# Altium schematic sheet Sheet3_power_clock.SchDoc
size A3
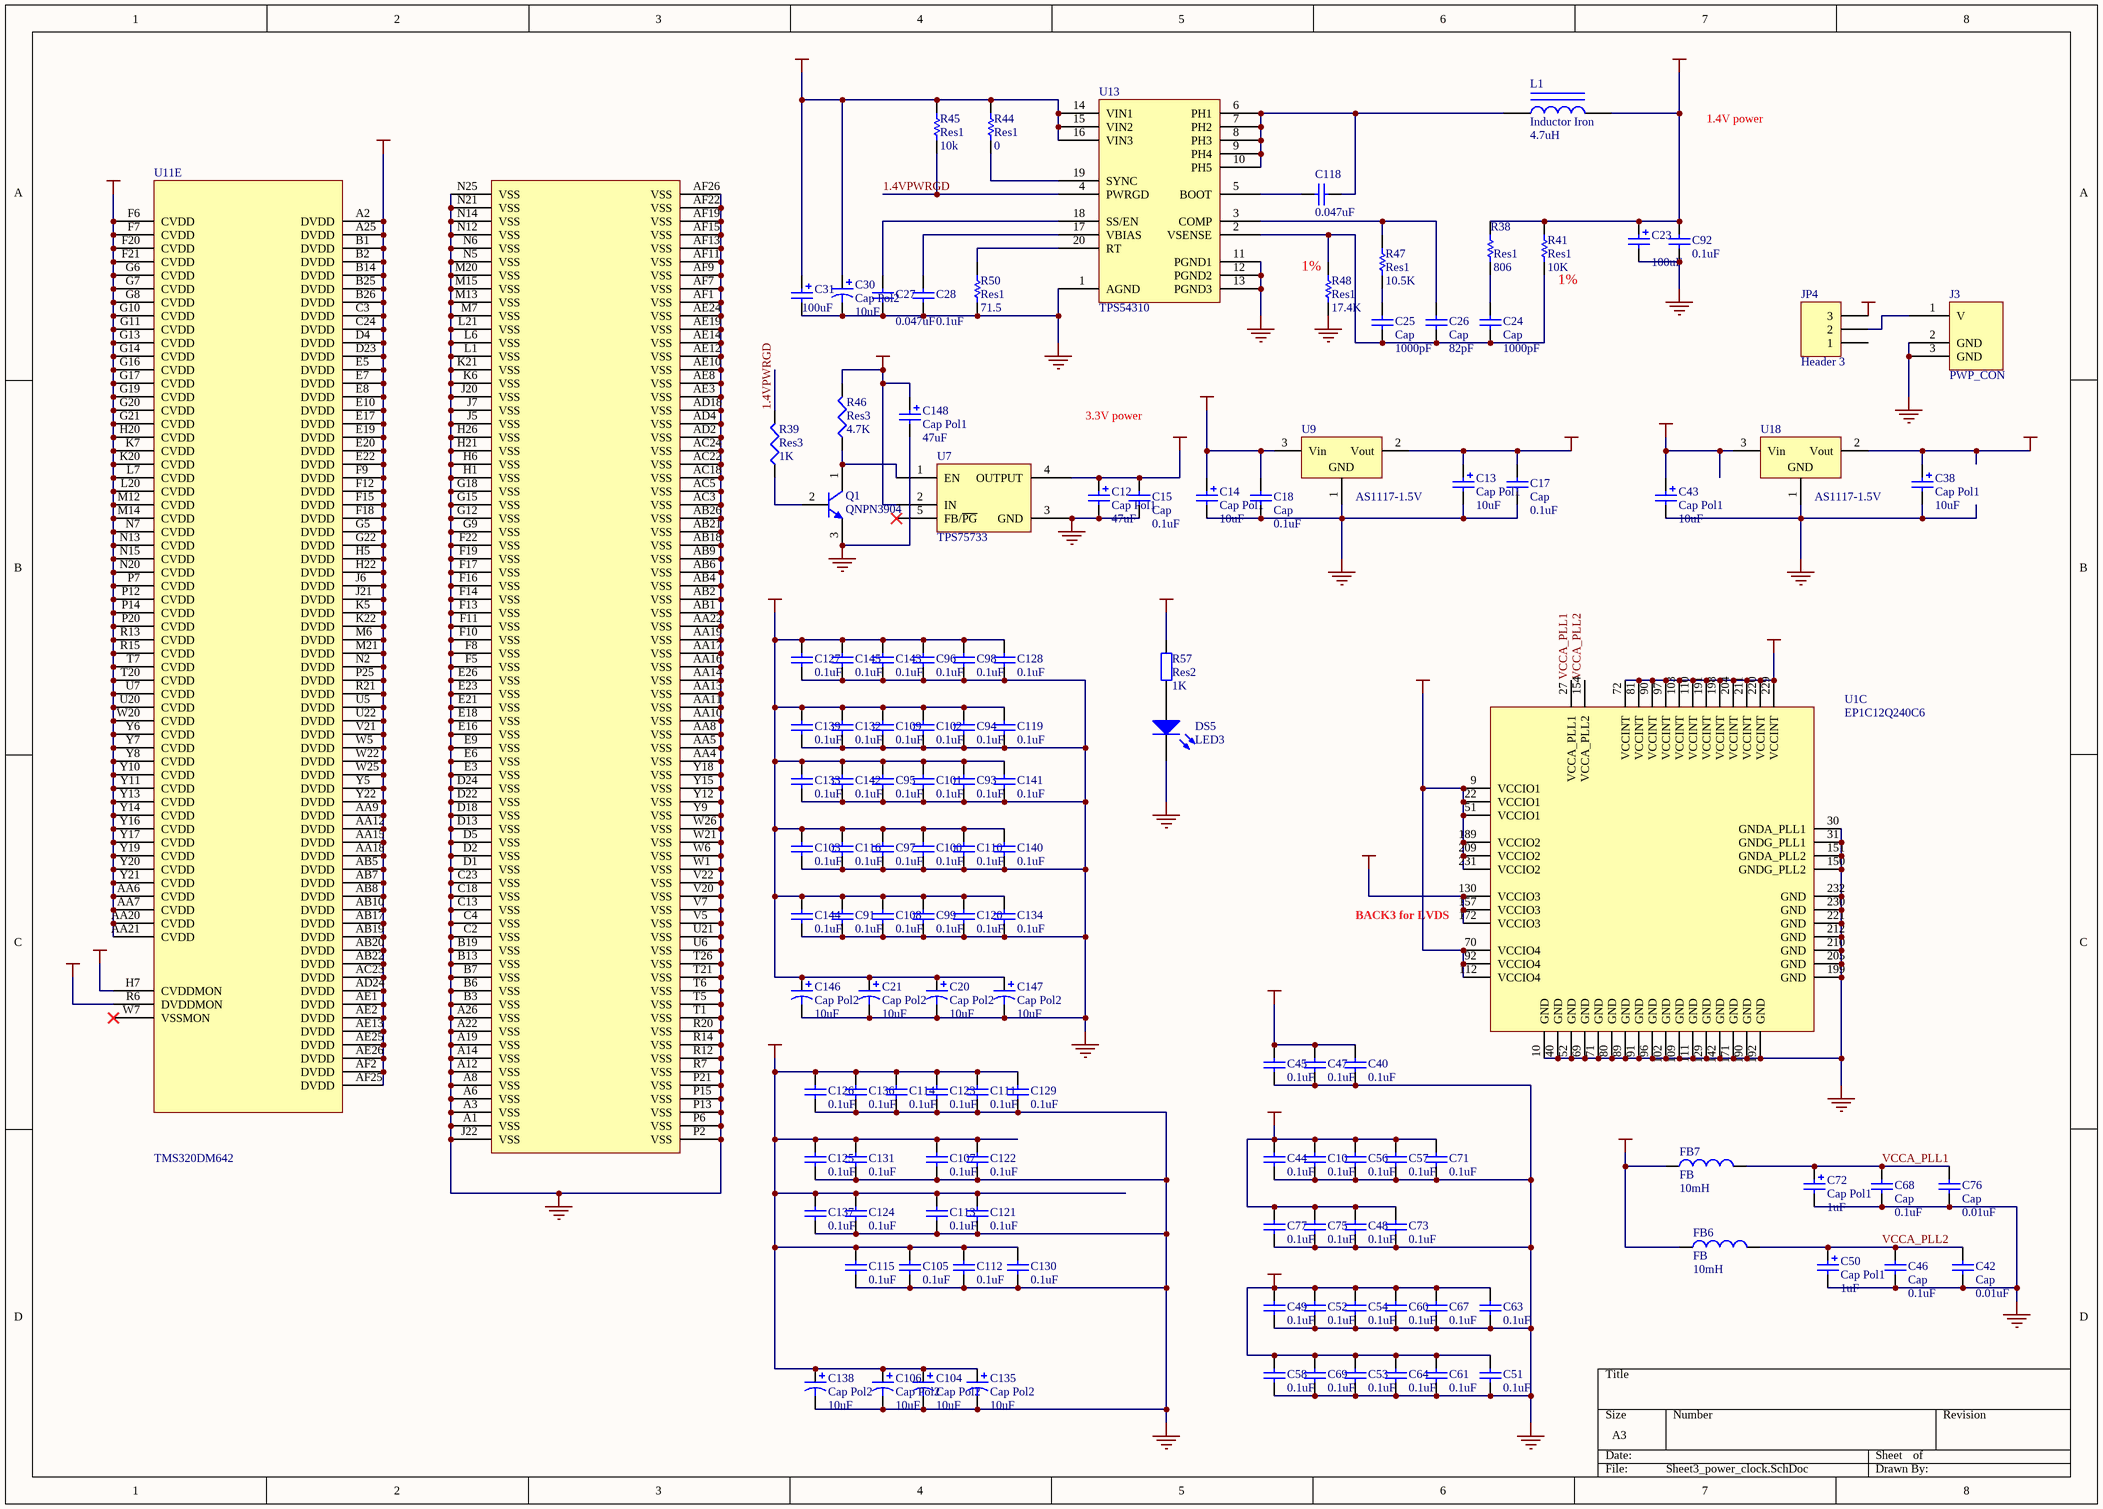
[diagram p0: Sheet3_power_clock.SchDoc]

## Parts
C10  value 0.1uF  [0603]  (hidden comment: Cap)
C12  Cap Pol1  value 47uF  [CC3216-1206]
C13  Cap Pol1  value 10uF  [CC3216-1206]
C14  Cap Pol1  value 10uF  [CC3216-1206]
C15  Cap  value 0.1uF  [C1608-0603]
C17  Cap  value 0.1uF  [C1608-0603]
C18  Cap  value 0.1uF  [C1608-0603]
C20  Cap Pol2  value 10uF  [CC3216-1206]
C21  Cap Pol2  value 10uF  [CC3216-1206]
C23  value 100uF  [CC6032]  (hidden comment: Cap Pol1)
C24  Cap  value 1000pF  [C1608-0603]
C25  Cap  value 1000pF  [C1608-0603]
C26  Cap  value 82pF  [C1608-0603]
C27  value 0.047uF  [C1608-0603]  (hidden comment: Cap)
C28  value 0.1uF  [C1608-0603]  (hidden comment: Cap)
C30  Cap Pol2  value 10uF  [CC3216-1206]
C31  value 100uF  [CC6032]  (hidden comment: Cap Pol1)
C38  Cap Pol1  value 10uF  [CC3216-1206]
C40  value 0.1uF  [0603]  (hidden comment: Cap)
C42  Cap  value 0.01uF  [C1608-0603]
C43  Cap Pol1  value 10uF  [CC3216-1206]
C44  value 0.1uF  [0603]  (hidden comment: Cap)
C45  value 0.1uF  [0603]  (hidden comment: Cap)
C46  Cap  value 0.1uF  [C1608-0603]
C47  value 0.1uF  [0603]  (hidden comment: Cap)
C48  value 0.1uF  [0603]  (hidden comment: Cap)
C49  value 0.1uF  [0603]  (hidden comment: Cap)
C50  Cap Pol1  value 1uF  [C1608-0603]
C51  value 0.1uF  [0603]  (hidden comment: Cap)
C52  value 0.1uF  [0603]  (hidden comment: Cap)
C53  value 0.1uF  [0603]  (hidden comment: Cap)
C54  value 0.1uF  [0603]  (hidden comment: Cap)
C56  value 0.1uF  [0603]  (hidden comment: Cap)
C57  value 0.1uF  [0603]  (hidden comment: Cap)
C58  value 0.1uF  [0603]  (hidden comment: Cap)
C60  value 0.1uF  [0603]  (hidden comment: Cap)
C61  value 0.1uF  [0603]  (hidden comment: Cap)
C63  value 0.1uF  [0603]  (hidden comment: Cap)
C64  value 0.1uF  [0603]  (hidden comment: Cap)
C67  value 0.1uF  [0603]  (hidden comment: Cap)
C68  Cap  value 0.1uF  [C1608-0603]
C69  value 0.1uF  [0603]  (hidden comment: Cap)
C71  value 0.1uF  [0603]  (hidden comment: Cap)
C72  Cap Pol1  value 1uF  [C1608-0603]
C73  value 0.1uF  [0603]  (hidden comment: Cap)
C75  value 0.1uF  [0603]  (hidden comment: Cap)
C76  Cap  value 0.01uF  [C1608-0603]
C77  value 0.1uF  [0603]  (hidden comment: Cap)
C91  value 0.1uF  [0603]  (hidden comment: Cap)
C92  value 0.1uF  [C1608-0603]  (hidden comment: Cap)
C93  value 0.1uF  [0603]  (hidden comment: Cap)
C94  value 0.1uF  [0603]  (hidden comment: Cap)
C95  value 0.1uF  [0603]  (hidden comment: Cap)
C96  value 0.1uF  [0603]  (hidden comment: Cap)
C97  value 0.1uF  [0603]  (hidden comment: Cap)
C98  value 0.1uF  [0603]  (hidden comment: Cap)
C99  value 0.1uF  [0603]  (hidden comment: Cap)
C100  value 0.1uF  [0603]  (hidden comment: Cap)
C101  value 0.1uF  [0603]  (hidden comment: Cap)
C102  value 0.1uF  [0603]  (hidden comment: Cap)
C103  value 0.1uF  [0603]  (hidden comment: Cap)
C104  Cap Pol2  value 10uF  [CC3216-1206]
C105  value 0.1uF  [0603]  (hidden comment: Cap)
C106  Cap Pol2  value 10uF  [CC3216-1206]
C107  value 0.1uF  [0603]  (hidden comment: Cap)
C108  value 0.1uF  [0603]  (hidden comment: Cap)
C109  value 0.1uF  [0603]  (hidden comment: Cap)
C110  value 0.1uF  [0603]  (hidden comment: Cap)
C111  value 0.1uF  [0603]  (hidden comment: Cap)
C112  value 0.1uF  [0603]  (hidden comment: Cap)
C113  value 0.1uF  [0603]  (hidden comment: Cap)
C114  value 0.1uF  [0603]  (hidden comment: Cap)
C115  value 0.1uF  [0603]  (hidden comment: Cap)
C116  value 0.1uF  [0603]  (hidden comment: Cap)
C118  value 0.047uF  [C1608-0603]  (hidden comment: Cap)
C119  value 0.1uF  [0603]  (hidden comment: Cap)
C120  value 0.1uF  [0603]  (hidden comment: Cap)
C121  value 0.1uF  [0603]  (hidden comment: Cap)
C122  value 0.1uF  [0603]  (hidden comment: Cap)
C123  value 0.1uF  [0603]  (hidden comment: Cap)
C124  value 0.1uF  [0603]  (hidden comment: Cap)
C125  value 0.1uF  [0603]  (hidden comment: Cap)
C126  value 0.1uF  [0603]  (hidden comment: Cap)
C127  value 0.1uF  [0603]  (hidden comment: Cap)
C128  value 0.1uF  [0603]  (hidden comment: Cap)
C129  value 0.1uF  [0603]  (hidden comment: Cap)
C130  value 0.1uF  [0603]  (hidden comment: Cap)
C131  value 0.1uF  [0603]  (hidden comment: Cap)
C132  value 0.1uF  [0603]  (hidden comment: Cap)
C133  value 0.1uF  [0603]  (hidden comment: Cap)
C134  value 0.1uF  [0603]  (hidden comment: Cap)
C135  Cap Pol2  value 10uF  [CC3216-1206]
C136  value 0.1uF  [0603]  (hidden comment: Cap)
C137  value 0.1uF  [0603]  (hidden comment: Cap)
C138  Cap Pol2  value 10uF  [CC3216-1206]
C139  value 0.1uF  [0603]  (hidden comment: Cap)
C140  value 0.1uF  [0603]  (hidden comment: Cap)
C141  value 0.1uF  [0603]  (hidden comment: Cap)
C142  value 0.1uF  [0603]  (hidden comment: Cap)
C143  value 0.1uF  [0603]  (hidden comment: Cap)
C144  value 0.1uF  [0603]  (hidden comment: Cap)
C145  value 0.1uF  [0603]  (hidden comment: Cap)
C146  Cap Pol2  value 10uF  [CC3216-1206]
C147  Cap Pol2  value 10uF  [CC3216-1206]
C148  Cap Pol1  value 47uF  [CC3216-1206]
DS5  LED3  [SMD _LED]
FB6  FB  value 10mH  [C1608-0603]
FB7  FB  value 10mH  [C1608-0603]
J3  PWP_CON  [POWER]
JP4  Header 3  [SWITCH3]
L1  Inductor Iron  value 4.7uH  [L44.7uH]
Q1  QNPN3904  [SO-G3 for NPN]
R38  Res1  value 806  [CR1608-0603]
R39  Res3  value 1K  [CR1608-0603]
R41  Res1  value 10K  [CR1608-0603]
R44  Res1  value 0  [CR1608-0603]
R45  Res1  value 10k  [CR1608-0603]
R46  Res3  value 4.7K  [CR1608-0603]
R47  Res1  value 10.5K  [CR1608-0603]
R48  Res1  value 17.4K  [CR1608-0603]
R50  Res1  value 71.5  [CR1608-0603]
R57  Res2  value 1K  [CR1608-0603]
U1  EP1C12Q240C6  [PQFP240]  (part C of 4)
U7  TPS75733  [SOT23-5S]
U9  AS1117-1.5V  [LM1117]
U11  TMS320DM642  [GNZ548]  (part E of 5)
U13  TPS54310  [PWP20]
U18  AS1117-1.5V  [LM1117]

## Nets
GND: C10.2 C12.2 C13.2 C14.2 C15.1 C17.1 C18.1 C20.2 C21.2 C23.2 C27.1 C28.1 C30.2 C31.2 C38.2 C40.2 C42.1 C43.2 C44.2 C45.2 C46.1 C47.2 C48.2 C49.2 C50.2 C51.2 C52.2 C53.2 C54.2 C56.2 C57.2 C58.2 C60.2 C61.2 C63.2 C64.2 C67.2 C68.1 C69.2 C71.2 C72.2 C73.2 C75.2 C76.1 C77.2 C91.2 C92.1 C93.2 C94.2 C95.2 C96.2 C97.2 C98.2 C99.2 C100.2 C101.2 C102.2 C103.2 C104.2 C105.1 C106.2 C107.2 C108.2 C109.2 C110.2 C111.2 C112.1 C113.2 C114.2 C115.2 C116.2 C119.2 C120.2 C121.2 C122.2 C123.2 C124.2 C125.2 C126.2 C127.2 C128.2 C129.2 C130.1 C131.2 C132.2 C133.2 C134.2 C135.2 C136.2 C137.2 C138.2 C139.2 C140.2 C141.2 C142.2 C143.2 C144.2 C145.2 C146.2 C147.2 C148.2 DS5.2(K) J3.2(GND) J3.3(GND) Q1.3(E) R48.1 R50.1 U1.10(GND) U1.30(GNDA_PLL1) U1.31(GNDG_PLL1) U1.40(GND) U1.52(GND) U1.69(GND) U1.71(GND) U1.80(GND) U1.89(GND) U1.91(GND) U1.96(GND) U1.102(GND) U1.109(GND) U1.111(GND) U1.129(GND) U1.142(GND) U1.150(GNDG_PLL2) U1.151(GNDA_PLL2) U1.171(GND) U1.190(GND) U1.192(GND) U1.199(GND) U1.205(GND) U1.210(GND) U1.212(GND) U1.221(GND) U1.230(GND) U1.232(GND) U7.3(GND) U9.1(GND) U11.A1(VSS) U11.A3(VSS) U11.A6(VSS) U11.A8(VSS) U11.A12(VSS) U11.A14(VSS) U11.A19(VSS) U11.A22(VSS) U11.A26(VSS) U11.AA4(VSS) U11.AA5(VSS) U11.AA8(VSS) U11.AA10(VSS) U11.AA11(VSS) U11.AA13(VSS) U11.AA14(VSS) U11.AA16(VSS) U11.AA17(VSS) U11.AA19(VSS) U11.AA22(VSS) U11.AB1(VSS) U11.AB2(VSS) U11.AB4(VSS) U11.AB6(VSS) U11.AB9(VSS) U11.AB18(VSS) U11.AB21(VSS) U11.AB26(VSS) U11.AC3(VSS) U11.AC5(VSS) U11.AC18(VSS) U11.AC22(VSS) U11.AC24(VSS) U11.AD2(VSS) U11.AD4(VSS) U11.AD18(VSS) U11.AE3(VSS) U11.AE8(VSS) U11.AE10(VSS) U11.AE12(VSS) U11.AE14(VSS) U11.AE19(VSS) U11.AE24(VSS) U11.AF1(VSS) U11.AF7(VSS) U11.AF9(VSS) U11.AF11(VSS) U11.AF13(VSS) U11.AF15(VSS) U11.AF19(VSS) U11.AF22(VSS) U11.AF26(VSS) U11.B3(VSS) U11.B6(VSS) U11.B7(VSS) U11.B13(VSS) U11.B19(VSS) U11.C2(VSS) U11.C4(VSS) U11.C13(VSS) U11.C18(VSS) U11.C23(VSS) U11.D1(VSS) U11.D2(VSS) U11.D5(VSS) U11.D13(VSS) U11.D18(VSS) U11.D22(VSS) U11.D24(VSS) U11.E3(VSS) U11.E6(VSS) U11.E9(VSS) U11.E16(VSS) U11.E18(VSS) U11.E21(VSS) U11.E23(VSS) U11.E26(VSS) U11.F5(VSS) U11.F8(VSS) U11.F10(VSS) U11.F11(VSS) U11.F13(VSS) U11.F14(VSS) U11.F16(VSS) U11.F17(VSS) U11.F19(VSS) U11.F22(VSS) U11.G9(VSS) U11.G12(VSS) U11.G15(VSS) U11.G18(VSS) U11.H1(VSS) U11.H6(VSS) U11.H21(VSS) U11.H26(VSS) U11.J5(VSS) U11.J7(VSS) U11.J20(VSS) U11.J22(VSS) U11.K6(VSS) U11.K21(VSS) U11.L1(VSS) U11.L6(VSS) U11.L21(VSS) U11.M7(VSS) U11.M13(VSS) U11.M15(VSS) U11.M20(VSS) U11.N5(VSS) U11.N6(VSS) U11.N12(VSS) U11.N14(VSS) U11.N21(VSS) U11.N25(VSS) U11.P2(VSS) U11.P6(VSS) U11.P13(VSS) U11.P15(VSS) U11.P21(VSS) U11.R7(VSS) U11.R12(VSS) U11.R14(VSS) U11.R20(VSS) U11.T1(VSS) U11.T5(VSS) U11.T6(VSS) U11.T21(VSS) U11.T26(VSS) U11.U6(VSS) U11.U21(VSS) U11.V5(VSS) U11.V7(VSS) U11.V20(VSS) U11.V22(VSS) U11.W1(VSS) U11.W6(VSS) U11.W21(VSS) U11.W26(VSS) U11.Y9(VSS) U11.Y12(VSS) U11.Y15(VSS) U11.Y18(VSS) U13.1(AGND) U13.11(PGND1) U13.12(PGND2) U13.13(PGND3) U18.1(GND)
V1.4: C23.1 C92.2 C104.1 C105.2 C106.1 C107.1 C111.1 C112.2 C113.1 C114.1 C115.1 C121.1 C122.1 C123.1 C124.1 C125.1 C126.1 C129.1 C130.2 C131.1 C135.1 C136.1 C137.1 C138.1 L1.2 R38.2 R41.2 U11.AA6(CVDD) U11.AA7(CVDD) U11.AA20(CVDD) U11.AA21(CVDD) U11.F6(CVDD) U11.F7(CVDD) U11.F20(CVDD) U11.F21(CVDD) U11.G6(CVDD) U11.G7(CVDD) U11.G8(CVDD) U11.G10(CVDD) U11.G11(CVDD) U11.G13(CVDD) U11.G14(CVDD) U11.G16(CVDD) U11.G17(CVDD) U11.G19(CVDD) U11.G20(CVDD) U11.G21(CVDD) U11.H7(CVDDMON) U11.H20(CVDD) U11.K7(CVDD) U11.K20(CVDD) U11.L7(CVDD) U11.L20(CVDD) U11.M12(CVDD) U11.M14(CVDD) U11.N7(CVDD) U11.N13(CVDD) U11.N15(CVDD) U11.N20(CVDD) U11.P7(CVDD) U11.P12(CVDD) U11.P14(CVDD) U11.P20(CVDD) U11.R13(CVDD) U11.R15(CVDD) U11.T7(CVDD) U11.T20(CVDD) U11.U7(CVDD) U11.U20(CVDD) U11.W20(CVDD) U11.Y6(CVDD) U11.Y7(CVDD) U11.Y8(CVDD) U11.Y10(CVDD) U11.Y11(CVDD) U11.Y13(CVDD) U11.Y14(CVDD) U11.Y16(CVDD) U11.Y17(CVDD) U11.Y19(CVDD) U11.Y20(CVDD) U11.Y21(CVDD)
V1.5: C13.1 C17.2 C49.1 C51.1 C52.1 C53.1 C54.1 C58.1 C60.1 C61.1 C63.1 C64.1 C67.1 C69.1 FB6.1 FB7.1 U1.72(VCCINT) U1.81(VCCINT) U1.90(VCCINT) U1.97(VCCINT) U1.103(VCCINT) U1.110(VCCINT) U1.191(VCCINT) U1.198(VCCINT) U1.204(VCCINT) U1.211(VCCINT) U1.220(VCCINT) U1.229(VCCINT) U9.2(Vout)
V2.5: C38.1 C40.1 C45.1 C47.1 U1.130(VCCIO3) U1.157(VCCIO3) U1.172(VCCIO3) U18.2(Vout)
V3.3: C10.1 C12.1 C15.2 C20.1 C21.1 C44.1 C48.1 C56.1 C57.1 C71.1 C73.1 C75.1 C77.1 C91.1 C93.1 C94.1 C95.1 C96.1 C97.1 C98.1 C99.1 C100.1 C101.1 C102.1 C103.1 C108.1 C109.1 C110.1 C116.1 C119.1 C120.1 C127.1 C128.1 C132.1 C133.1 C134.1 C139.1 C140.1 C141.1 C142.1 C143.1 C144.1 C145.1 C146.1 C147.1 U1.9(VCCIO1) U1.22(VCCIO1) U1.51(VCCIO1) U1.70(VCCIO4) U1.92(VCCIO4) U1.112(VCCIO4) U1.189(VCCIO2) U1.209(VCCIO2) U1.231(VCCIO2) U7.4(OUTPUT) U11.A2(DVDD) U11.A25(DVDD) U11.AA9(DVDD) U11.AA12(DVDD) U11.AA15(DVDD) U11.AA18(DVDD) U11.AB5(DVDD) U11.AB7(DVDD) U11.AB8(DVDD) U11.AB10(DVDD) U11.AB17(DVDD) U11.AB19(DVDD) U11.AB20(DVDD) U11.AB22(DVDD) U11.AC23(DVDD) U11.AD24(DVDD) U11.AE1(DVDD) U11.AE2(DVDD) U11.AE13(DVDD) U11.AE25(DVDD) U11.AE26(DVDD) U11.AF2(DVDD) U11.AF25(DVDD) U11.B1(DVDD) U11.B2(DVDD) U11.B14(DVDD) U11.B25(DVDD) U11.B26(DVDD) U11.C3(DVDD) U11.C24(DVDD) U11.D4(DVDD) U11.D23(DVDD) U11.E5(DVDD) U11.E7(DVDD) U11.E8(DVDD) U11.E10(DVDD) U11.E17(DVDD) U11.E19(DVDD) U11.E20(DVDD) U11.E22(DVDD) U11.F9(DVDD) U11.F12(DVDD) U11.F15(DVDD) U11.F18(DVDD) U11.G5(DVDD) U11.G22(DVDD) U11.H5(DVDD) U11.H22(DVDD) U11.J6(DVDD) U11.J21(DVDD) U11.K5(DVDD) U11.K22(DVDD) U11.M6(DVDD) U11.M21(DVDD) U11.N2(DVDD) U11.P25(DVDD) U11.R6(DVDDMON) U11.R21(DVDD) U11.U5(DVDD) U11.U22(DVDD) U11.V21(DVDD) U11.W5(DVDD) U11.W22(DVDD) U11.W25(DVDD) U11.Y5(DVDD) U11.Y22(DVDD)
V5: C14.1 C18.2 C30.1 C31.1 C43.1 C148.1 JP4.3 R44.2 R45.1 R46.2 R57.2 U7.2(IN) U9.3(Vin) U13.14(VIN1) U13.15(VIN2) U13.16(VIN3) U18.3(Vin)
1.4VPWRGD: R39.2 R45.2 U13.4(PWRGD)
VCCA_PLL1: C68.2 C72.1 C76.2 FB7.2 U1.27(VCCA_PLL1)
VCCA_PLL2: C42.2 C46.2 C50.1 FB6.2 U1.154(VCCA_PLL2)
NetC24_1: C24.1 C25.1 C26.1 R41.1 R48.2 U13.2(VSENSE)
NetC24_2: C24.2 R38.1
NetC25_2: C25.2 R47.1
NetC26_2: C26.2 R47.2 U13.3(COMP)
NetC27_2: C27.2 U13.18(SS/EN)
NetC28_2: C28.2 U13.17(VBIAS)
NetC118_1: C118.1 U13.5(BOOT)
NetC118_2: C118.2 L1.1 U13.6(PH1) U13.7(PH2) U13.8(PH3) U13.9(PH4) U13.10(PH5)
NetDS5_1: DS5.1(A) R57.1
NetJ3_1: J3.1(V) JP4.2
NetQ1_1: Q1.1(C) R46.1 U7.1(EN)
NetQ1_2: Q1.2(B) R39.1
NetR44_1: R44.1 U13.19(SYNC)
NetR50_2: R50.2 U13.20(RT)

Not connected (* = marked no-connect by the designer): JP4 1; U7 5(FB/~{PG})*; U11 W7(VSSMON)*

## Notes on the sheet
- 1.4V power
- (near R48) 1%
- (near R41) 1%
- 3.3V power
- (near U1) BACK3 for LVDS

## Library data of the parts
C10 C15 C17 C18 C24-C28 C40 C42 C44-C49 C51-C54 C56-C58 C60 C61 C63 C64 C67-C69 C71 C73 C75-C77 C91-C103 C105 C107-C116 C118-C134 C136 C137 C139-C145 = Cap: Capacitor
C12-C14 C23 C31 C38 C43 C50 C72 C148 = Cap Pol1: Polarized Capacitor (Radial)
C20 C21 C30 C104 C106 C135 C138 C146 C147 = Cap Pol2: Polarized Capacitor (Axial)
DS5 = LED3: Typical BLUE SiC LED; Revision 1: Jul-2002: Re-released for DXP Platform.; Revision 2: 17-Dec-2003: PCB Footprint replaced.
FB6 FB7 = Inductor
JP4 = Header 3: Header, 3-Pin
L1 = Inductor Iron: Magnetic-Core Inductor
Q1 = QNPN: NPN Bipolar Transistor; Code - JEDEC: SOT-23
R38 R41 R44 R45 R47 R48 R50 = Res1: Resistor
R39 R46 = Res3: Resistor
R57 = Res2: Resistor
U1 = EP1C12Q240C6: Cyclone Family, 1.5V FPGA, 173 I/O Pins, 2 x PLLs, Commercial Grade, Speed Grade 6; Package Information: Latest Revision: ver11.0, Feb-2003; Code - JEDEC: MS-029-GA
U9 U18 = Volt Reg: Voltage Regulator; Code - JEDEC: SMD-220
